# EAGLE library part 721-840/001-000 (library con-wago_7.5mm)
Serie 721, Stiftleiste (für Leiterplatten) Einlötstift abgewinkelt 1 x 1 mm / Series 721, Male header (for PCBs) Angled solder pin 1 x 1 mm Polzahl / Pole No.: 10 Rastermaß / Pitch: 7.5 mm Bemessungsspannung / Rated Voltage: 630 V Nennstrom / Nominal Current: 12 A Lötstiftlänge: / Solder Pin Length: 3.8 mm Farbe / Color: lichtgrau / light gray Stand: 01.01.2012. Die jeweils aktuellen Daten zu diesem Artikel finden Sie in unserem Produktkatalog, den Sie unter www.wago.com einsehen können. As of: 01/01/2012. Please find the newest data for this article in our product catalogue, which can be viewed under www.wago.com.
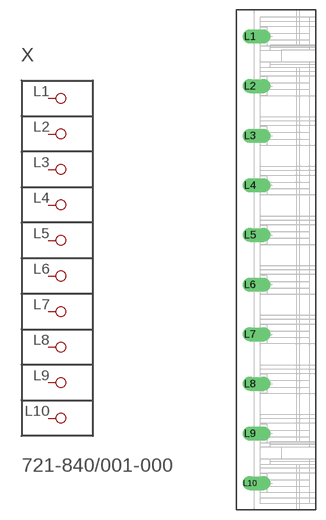
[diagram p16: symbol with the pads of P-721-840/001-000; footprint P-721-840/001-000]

Designator prefix X

## 721-840/001-000  [P-721-840/001-000]
L1  P1
L2  P2
L3  P3
L4  P4
L5  P5
L6  P6
L7  P7
L8  P8
L9  P9
L10  P10

## Footprint P-721-840/001-000 (pad centres in mm)
drill 1.4 offset: L1 -4,33.75; L2 -4,26.25; L3 -4,18.75; L4 -4,11.25; L5 -4,3.75; L6 -4,-3.75; L7 -4,-11.25; L8 -4,-18.75; L9 -4,-26.25; L10 -4,-33.75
